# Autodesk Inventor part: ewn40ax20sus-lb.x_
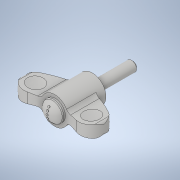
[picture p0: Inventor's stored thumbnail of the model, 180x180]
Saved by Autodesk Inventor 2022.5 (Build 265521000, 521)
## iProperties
Created: 2021-08
Part Number: ewn40ax20sus-lb.x_
Material: 一般
Document SubType Name: Modeling
Designer: ImaoCorp
Density: 1 g/cm^3
Appearance: 既定
Sending System: SOLIDWORKS 2019-2019304
MC: AMD64
MC_MODEL: Intel64 Family 6 Model 60 Stepping 3, GenuineIntel
OS: Windows_NT
FRU: Parasolid Version 31.0, build 290,  9- 1-2019
FORMAT: text
GUISE: transmit
KEY: ewn40ax20sus-lb
FILE: ewn40ax20sus-lb.x_t
DATE: Wed Aug 11 15:03:07 2021
Author: ImaoCorp
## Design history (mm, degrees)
feature "Base1"
node "ソリッド1"
